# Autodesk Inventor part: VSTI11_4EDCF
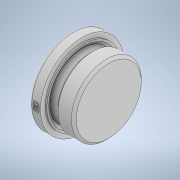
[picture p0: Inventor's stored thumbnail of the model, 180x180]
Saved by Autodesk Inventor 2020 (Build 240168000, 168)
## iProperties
Created: 2019-12
Part Number: VSTI11_4EDCF
Material: Generico
Description: STEP AP203
Document SubType Name: Modeling
Designer: carlo
Density: 1 g/cm^3
Appearance: Default
DataBaseUnit: MM
Title: p:/temp/worker_143/temp/exporttempdir_2124_363_o3emU/format_0/EO Verschluss-Stopfen fuer Einschraubloecher VSTI11_4EDCF.stp
Revision Number: NONE
Sending System: PARTsolutions
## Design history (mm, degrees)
feature "_EO Verschluss-Stopfen fuer Einschraubloecher VSTI11_4EDCF"
node "Piano di lavoro1"
node "Piano di lavoro2"
node "Asse di lavoro1"
node "Solido1"
other parameters: "d0" = 0, "d1" = 0
